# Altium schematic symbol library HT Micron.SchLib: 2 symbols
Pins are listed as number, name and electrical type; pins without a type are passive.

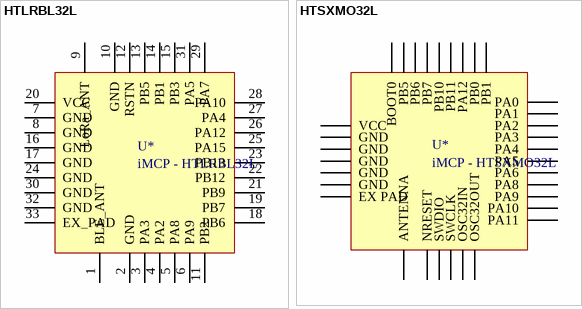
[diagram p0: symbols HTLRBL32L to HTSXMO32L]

## HTLRBL32L
designator U*, comment iMCP - HTLRBL32L
footprint HTLRBL32L (HTLRBL32L SiP)
pins: 1 BLE_ANT, 2 GND, 3 PA3, 4 PA2, 5 PA8, 6 PA9, 7 GND, 8 GND, 9 LoRa_ANT, 10 GND, 11 PB2, 12 RSTN, 13 PB5, 14 PB1, 15 PB3, 16 GND, 17 GND, 18 PB6, 19 PB7, 20 VCC, 21 PB9, 22 PB12, 23 PB13, 24 GND, 25 PA15, 26 PA12, 27 PA4, 28 PA10, 29 PA7, 30 GND, 31 PA5, 32 GND, 33 EX_PAD

## HTSXMO32L
designator U*, comment iMCP - HTSXMO32L
footprint HTSXMO32L (HTSXMO32L SiP)
pins: 1 ANTENNA, 2 GND, 3 PA11, 4 PA9, 5 PA10, 6 PB11, 7 PB0, 8 VCC, 9 PA8, 10 PA5, 11 PA3, 12 PA1, 13 PB10, 14 PA6, 15 PA4, 16 GND, 17 PA2, 18 PA0, 19 BOOT0, 20 PB5, 21 GND, 22 NRESET, 23 SWCLK, 24 SWDIO, 25 OSC32OUT, 26 OSC32IN, 27 GND, 28 PB1, 29 PB7, 30 PB6, 31 PA12, 32 GND, 33 EX PAD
